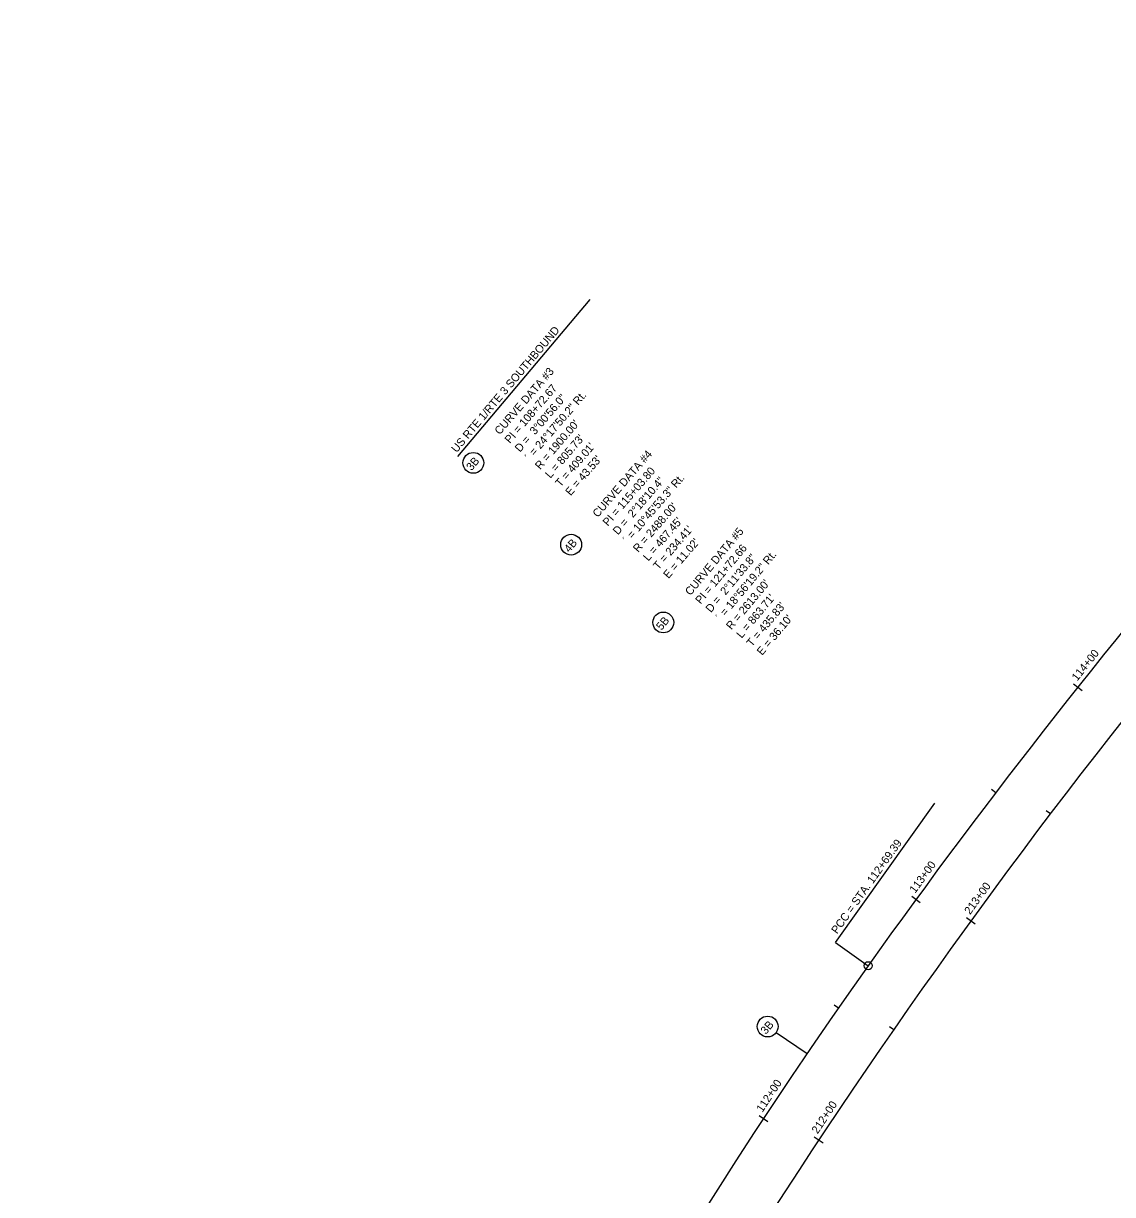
# Model space of a CAD drawing. Extents: x 1667099 to 1669772, y 337408 to 340124.
# Drawn here: x 1667390 to 1667798, y 338721.6 to 339160.5 of the extents above; entities that cross this region are included whole.
import ezdxf

# ---------------------------------------------------------------- set-up
doc = ezdxf.new("R2010")
doc.units = 0
for name, color, linetype in [('Alignment', 7, 'Continuous'), ('ANNOTATION', 7, 'Continuous'), ('D_Roadway_Centerline', 7, 'Continuous'), ('D_Roadway_Centerline_CurveData', 7, 'Continuous'), ('D_Roadway_Centerline_Flags', 7, 'Continuous'), ('D_Roadway_Centerline_Text', 7, 'Continuous'), ('S_Roadway_Edge_Pavement', 7, 'Continuous')]:
    doc.layers.add(name, color=color, linetype=linetype)

msp = doc.modelspace()

# ---------------------------------------------------------------- linework, layer by layer
at = {"layer": 'Alignment'}
msp.add_arc((1669660.52, 337433.83), 2367, 133.53618, 147.66044, dxfattribs=at)
at = {"layer": 'ANNOTATION'}
for p, q in [((1667552.73, 338998.22), (1667602.32, 339057.01)), ((1667672.02, 338782.4), (1667683.56, 338774.54))]:
    msp.add_line(p, q, dxfattribs=at)
for centre in [(1667558.54, 338995.84), (1667595.17, 338965.18), (1667629.68, 338936.05), (1667668.79, 338784.6)]:
    msp.add_circle(centre, 3.9, dxfattribs=at)
at = {"layer": 'D_Roadway_Centerline'}
for centre, radius, start, end in [((1669733, 337364.06), 2488, 133.776, 144.54079), ((1669660.52, 337433.83), 2367, 133.53618, 147.66044), ((1669254.06, 337705.17), 1900, 144.54079, 168.83807)]:
    msp.add_arc(centre, radius, start, end, dxfattribs=at)
at = {"layer": 'D_Roadway_Centerline_Flags'}
msp.add_line((1667694.23, 338816.11), (1667731.39, 338868.28), dxfattribs=at)
msp.add_lwpolyline([(1667694.23, 338816.11), (1667706.45, 338807.41)], dxfattribs=at)
msp.add_circle((1667706.45, 338807.41), 1.5, dxfattribs=at)
at = {"layer": 'D_Roadway_Centerline_Text'}
for points in [[(1667783.41, 338913), (1667786.55, 338910.51)], [(1667752.68, 338873.51), (1667754.27, 338872.3)], [(1667773.16, 338865.62), (1667774.75, 338864.41)], [(1667722.75, 338833.41), (1667725.98, 338831.05)], [(1667743.33, 338825.43), (1667746.57, 338823.08)], [(1667693.64, 338792.7), (1667695.29, 338791.56)], [(1667714.37, 338784.63), (1667716.01, 338783.49)], [(1667665.57, 338751.27), (1667668.91, 338749.07)], [(1667686.27, 338743.22), (1667689.6, 338741.01)]]:
    msp.add_lwpolyline(points, dxfattribs=at)
at = {"layer": 'S_Roadway_Edge_Pavement'}
for centre, radius, start, end in [((1669733, 337364.06), 2488, 133.776, 144.54079), ((1669254.06, 337705.17), 1900, 144.54079, 168.83807)]:
    msp.add_arc(centre, radius, start, end, dxfattribs=at)

# ---------------------------------------------------------------- texts
at = {"layer": 'ANNOTATION'}
for s, p in [('US RTE 1/RTE 3 SOUTHBOUND', (1667552.26, 338999.45)), ('3B', (1667557.87, 338992.69)), ('4B', (1667594.5, 338962.03)), ('5B', (1667629.01, 338932.89)), ('3B', (1667668.12, 338781.44))]:
    msp.add_text(s, height=3, rotation=49.8502, dxfattribs=at).set_placement(p)
at = {"layer": 'D_Roadway_Centerline_CurveData'}
for s, rotation, p in [('CURVE DATA #3', 49.2618, (1667568.45, 339006.15)), ('PI = 108+72.67', 49.2618, (1667572.24, 339002.89)), ('D =  3%%d00\'56.0"', 49.2618, (1667576.02, 338999.63)), ('´ = 24%%d17\'50.2" Rt.', 49.2618, (1667579.81, 338996.36)), ("R = 1900.00'", 49.2618, (1667583.6, 338993.1)), ("L = 805.73'", 49.2618, (1667587.39, 338989.84)), ("T = 409.01'", 49.2618, (1667591.18, 338986.58)), ('CURVE DATA #4', 49.1584, (1667605.16, 338975.17)), ("E = 43.53'", 49.2618, (1667594.97, 338983.31)), ('PI = 115+03.80', 49.1584, (1667608.95, 338971.9)), ('D =  2%%d18\'10.4"', 49.1584, (1667612.73, 338968.63)), ('´ = 10%%d45\'53.3" Rt.', 49.1584, (1667616.51, 338965.36)), ("R = 2488.00'", 49.1584, (1667620.3, 338962.09)), ("L = 467.45'", 49.1584, (1667624.08, 338958.82)), ("T = 234.41'", 49.1584, (1667627.86, 338955.55)), ('CURVE DATA #5', 50.1657, (1667639.85, 338945.91)), ("E = 11.02'", 49.1584, (1667631.64, 338952.28)), ('PI = 121+72.66', 50.1657, (1667643.69, 338942.7)), ('D =  2%%d11\'33.8"', 50.1657, (1667647.53, 338939.5)), ('´ = 18%%d56\'19.2" Rt.', 50.1657, (1667651.37, 338936.3)), ("R = 2613.00'", 50.1657, (1667655.21, 338933.09)), ("L = 863.71'", 50.1657, (1667659.05, 338929.89)), ("T = 435.83'", 50.1657, (1667662.89, 338926.69)), ("E = 36.10'", 50.1657, (1667666.73, 338923.48))]:
    msp.add_text(s, height=3, rotation=rotation, dxfattribs=at).set_placement(p)
at = {"layer": 'D_Roadway_Centerline_Flags'}
msp.add_text('PCC = STA. 112+69.39', height=3, rotation=54.5408, dxfattribs=at).set_placement((1667694.81, 338819.09))
at = {"layer": 'D_Roadway_Centerline_Text'}
for s, rotation, p in [('114+00', 51.5329, (1667784.74, 338913.86)), ('113+00', 53.8358, (1667724.04, 338834.33)), ('213+00', 54.0257, (1667744.62, 338826.35)), ('112+00', 56.6332, (1667666.81, 338752.24)), ('212+00', 56.4463, (1667687.52, 338744.19))]:
    msp.add_text(s, height=3, rotation=rotation, dxfattribs=at).set_placement(p)

doc.saveas('drawing.dxf')
